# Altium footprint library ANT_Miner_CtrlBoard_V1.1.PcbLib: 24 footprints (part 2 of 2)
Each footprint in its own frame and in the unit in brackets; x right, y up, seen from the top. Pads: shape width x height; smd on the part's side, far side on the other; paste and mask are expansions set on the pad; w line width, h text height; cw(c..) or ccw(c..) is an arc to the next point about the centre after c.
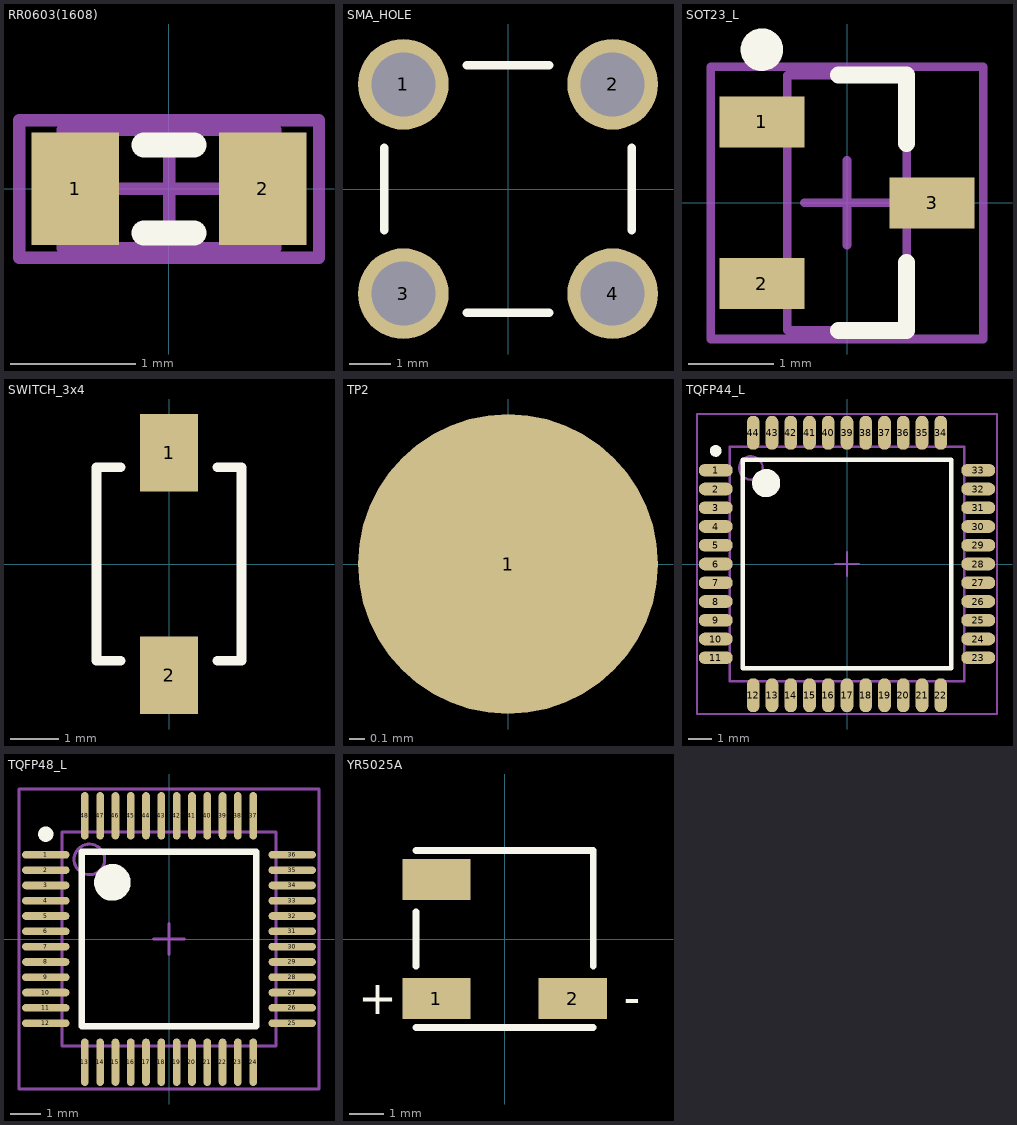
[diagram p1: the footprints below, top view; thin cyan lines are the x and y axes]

## RR0603(1608) [mm] "Chip Resistor, Body 1.6x0.8mm, IPC High Density"
height 0.6
pads (2):
  rect 0.7x0.9 smd: 1(-0.75,0) 2(0.75,0)
Top Overlay:
  lines w0.2: -0.2,-0.35 0.2,-0.35 ; -0.2,0.35 0.2,0.35
Mechanical 13:
  lines w0.1: -0.85,-0.475 0.85,-0.475 0.85,0.475 -0.85,0.475 -0.85,-0.475
Mechanical 15:
  lines w0.1: -0.475,0 0.475,0 ; 0,-0.475 0,0.475 ; -1.2,-0.55 1.2,-0.55 1.2,0.55 -1.2,0.55 -1.2,-0.55
3D body: height 0.6, standoff 0, extent -0.85,-0.475 0.85,0.475

## SMA_HOLE [mm] "SMA Socket Assembly Hole."
height 18.15
pads (4):
  round 2.2 hole 1.55: 1(-2.54,2.54) 2(2.54,2.54) 3(-2.54,-2.54) 4(2.54,-2.54)
Top Overlay:
  lines w0.203: -3,-1 -3,1 ; -1,-3 1,-3 ; -1,3 1,3 ; 3,-1 3,1

## SOT23_L [mm] "SOT23, 3-Leads, Body 2.9x1.3mm, Pitch 0.95mm, Lead Span 2.3mm - Reverse Pinning, IPC High Density"
height 1.1
pads (3):
  rect 1x0.6 smd: 1(-1,0.95) 2(-1,-0.95) 3(1,0)
Top Overlay:
  circle w0.25: c-1,1.8 r0.125
  lines w0.2: -0.1,-1.5 0.7,-1.5 0.7,-0.7 ; -0.1,1.5 0.7,1.5 0.7,0.7
Mechanical 13:
  lines w0.1: -0.7,-1.5 -0.7,1.5 0.7,1.5 0.7,-1.5 -0.7,-1.5
Mechanical 15:
  lines w0.1: -0.5,0 0.5,0 ; 0,-0.5 0,0.5 ; -1.6,-1.6 -1.6,1.6 1.6,1.6 1.6,-1.6 -1.6,-1.6
3D body: height 1.1, standoff 0, extent -0.7,-1.5 0.7,1.5

## SWITCH_3x4 [mm]
pads (2):
  rect 1.2x1.6 smd: 1(0,2.3) 2(0,-2.3)
Top Overlay:
  lines w0.203: -1,-2 -1.5,-2 -1.5,2 -1,2 ; 1,-2 1.5,-2 1.5,2 1,2

## TP2 [mm] "Test Point 2mm SMD"
height 18.15
pads (1):
  round 2 smd: 1(0,0)

## TQFP44_L [mm] "Thin QFP, 44-Leads, Body 10x10mm, Pitch 0.8mm, IPC High Density"
height 1.6
pads (44):
  oval 1.45x0.55 smd: 1(-5.6,4) 2(-5.6,3.2) 3(-5.6,2.4) 4(-5.6,1.6) 5(-5.6,0.8) 6(-5.6,0) 7(-5.6,-0.8) 8(-5.6,-1.6) 9(-5.6,-2.4) 10(-5.6,-3.2) 11(-5.6,-4) 23(5.6,-4) 24(5.6,-3.2) 25(5.6,-2.4) 26(5.6,-1.6) 27(5.6,-0.8) 28(5.6,0) 29(5.6,0.8) 30(5.6,1.6) 31(5.6,2.4) 32(5.6,3.2) 33(5.6,4)
  oval 0.55x1.45 smd: 12(-4,-5.6) 13(-3.2,-5.6) 14(-2.4,-5.6) 15(-1.6,-5.6) 16(-0.8,-5.6) 17(0,-5.6) 18(0.8,-5.6) 19(1.6,-5.6) 20(2.4,-5.6) 21(3.2,-5.6) 22(4,-5.6) 34(4,5.6) 35(3.2,5.6) 36(2.4,5.6) 37(1.6,5.6) 38(0.8,5.6) 39(0,5.6) 40(-0.8,5.6) 41(-1.6,5.6) 42(-2.4,5.6) 43(-3.2,5.6) 44(-4,5.6)
Top Overlay:
  circle w0.25: c-5.6,4.825 r0.125
  circle w0.6: c-3.45,3.45 r0.3
  lines w0.2: -4.45,-4.45 -4.45,4.45 4.45,4.45 4.45,-4.45 -4.45,-4.45
Mechanical 13:
  circle w0.1: c-4.1,4.1 r0.5
  lines w0.1: -5,-5 -5,5 5,5 5,-5 -5,-5
Mechanical 15:
  lines w0.1: -0.5,0 0.5,0 ; 0,-0.5 0,0.5 ; -6.4,-6.4 -6.4,6.4 6.4,6.4 6.4,-6.4 -6.4,-6.4
3D body: height 1.6, standoff 0, extent -5,-5 5,5

## TQFP48_L [mm]
height 0.9
pads (48):
  oval 1.55x0.25 smd: 1(-4.025,2.75) 2(-4.025,2.25) 3(-4.025,1.75) 4(-4.025,1.25) 5(-4.025,0.75) 6(-4.025,0.25) 7(-4.025,-0.25) 8(-4.025,-0.75) 9(-4.025,-1.25) 10(-4.025,-1.75) 11(-4.025,-2.25) 12(-4.025,-2.75) 25(4.025,-2.75) 26(4.025,-2.25) 27(4.025,-1.75) 28(4.025,-1.25) 29(4.025,-0.75) 30(4.025,-0.25) 31(4.025,0.25) 32(4.025,0.75) 33(4.025,1.25) 34(4.025,1.75) 35(4.025,2.25) 36(4.025,2.75)
  oval 0.25x1.55 smd: 13(-2.75,-4.025) 14(-2.25,-4.025) 15(-1.75,-4.025) 16(-1.25,-4.025) 17(-0.75,-4.025) 18(-0.25,-4.025) 19(0.25,-4.025) 20(0.75,-4.025) 21(1.25,-4.025) 22(1.75,-4.025) 23(2.25,-4.025) 24(2.75,-4.025) 37(2.75,4.025) 38(2.25,4.025) 39(1.75,4.025) 40(1.25,4.025) 41(0.75,4.025) 42(0.25,4.025) 43(-0.25,4.025) 44(-0.75,4.025) 45(-1.25,4.025) 46(-1.75,4.025) 47(-2.25,4.025) 48(-2.75,4.025)
Top Overlay:
  circle w0.25: c-4.025,3.425 r0.125
  circle w0.6: c-1.85,1.85 r0.3
  lines w0.2: -2.85,-2.85 -2.85,2.85 2.85,2.85 2.85,-2.85 -2.85,-2.85
Mechanical 13:
  circle w0.1: c-2.6,2.6 r0.5
  lines w0.1: -3.5,-3.5 -3.5,3.5 3.5,3.5 3.5,-3.5 -3.5,-3.5
Mechanical 15:
  lines w0.1: -0.5,0 0.5,0 ; 0,-0.5 0,0.5 ; -4.9,-4.9 -4.9,4.9 4.9,4.9 4.9,-4.9 -4.9,-4.9
3D body: height 1.6, standoff 0, extent -3.5,-3.5 3.5,3.5

## YR5025A [mm]
height 2.7
pads (3):
  rect 2x1.2 smd: 1(-2,-1.75) 2(2,-1.75) ""(-2,1.75)
Top Overlay:
  lines w0.203: -2.6,-2.6 2.6,-2.6 ; -2.6,-0.8 -2.6,0.8 ; -2.6,2.6 2.6,2.6 2.6,-0.8
  text "-" at 3.5,-2.2 h1
  text "+" at -4.3,-2.2 h1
